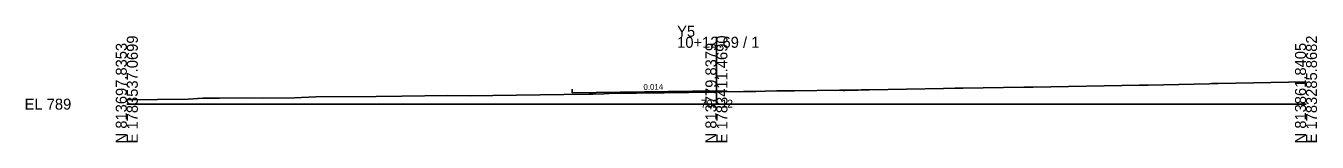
# Model space of a CAD drawing. Extents: x -26 to 1603, y -10 to 6526.
# Drawn here: x -25.7 to 302.8, y 490.3 to 520 of the extents above; entities that cross this region are included whole.
import ezdxf

# ---------------------------------------------------------------- set-up
doc = ezdxf.new("R2010")
doc.units = 0
for name, color, linetype in [('Exist Cross Section Cell', 7, 'Continuous'), ('Exist XS Center Line Elevation Label', 7, 'Continuous'), ('Exist XS Ground Line', 7, 'Continuous'), ('Prop XS Dump Level', 7, 'Continuous'), ('Prop XS EOT Tick Mark', 7, 'Continuous'), ('Prop XS Finish Grade Pavement', 7, 'Continuous'), ('Prop XS SE Text', 7, 'Continuous'), ('Prop XS Subgrade Earthwork', 7, 'Continuous')]:
    doc.layers.add(name, color=color, linetype=linetype)

msp = doc.modelspace()

# ---------------------------------------------------------------- linework, layer by layer
at = {"layer": 'Exist Cross Section Cell'}
for p, q in [((150, 500), (150, 517.15)), ((0, 500), (150, 500)), ((150, 500), (300, 500))]:
    msp.add_line(p, q, dxfattribs=at)
at = {"layer": 'Exist XS Ground Line'}
for p, q in [((118.6, 502.56), (121.36, 502.66)), ((121.36, 502.66), (122.6, 502.7)), ((122.6, 502.7), (136.75, 502.9)), ((136.75, 502.9), (142.87, 503)), ((142.87, 503), (145.78, 503.04)), ((145.78, 503.04), (147.13, 503.06)), ((147.13, 503.06), (147.98, 503.07)), ((147.98, 503.07), (148.64, 503.08)), ((148.64, 503.08), (149.03, 503.09)), ((149.03, 503.09), (150.13, 503.13)), ((150.13, 503.13), (151.42, 503.14)), ((151.42, 503.14), (156.9, 503.22)), ((156.9, 503.22), (157.33, 503.23)), ((157.33, 503.23), (157.84, 503.23)), ((157.84, 503.23), (158.63, 503.24)), ((158.63, 503.24), (160, 503.26)), ((160, 503.26), (162.37, 503.31)), ((162.37, 503.31), (165.34, 503.35)), ((165.34, 503.35), (169.83, 503.41)), ((169.83, 503.41), (181.35, 503.54)), ((181.35, 503.54), (182.42, 503.56)), ((182.42, 503.56), (186.06, 503.57)), ((186.06, 503.57), (186.81, 503.64)), ((186.81, 503.64), (188.96, 503.65)), ((188.96, 503.65), (207.8, 503.97)), ((207.8, 503.97), (210.69, 504.04)), ((210.69, 504.04), (212.68, 504.05)), ((212.68, 504.05), (228.17, 504.31)), ((228.17, 504.31), (228.65, 504.31)), ((228.65, 504.31), (230.58, 504.34)), ((230.58, 504.34), (257.63, 504.81)), ((257.63, 504.81), (258.75, 504.83)), ((258.75, 504.83), (259.82, 504.87)), ((259.82, 504.87), (275.42, 505.21)), ((275.42, 505.21), (275.99, 505.23)), ((275.99, 505.23), (276.76, 505.24)), ((276.76, 505.24), (277.68, 505.23)), ((277.68, 505.23), (300, 505.72)), ((0, 501.13), (15.64, 501.24)), ((15.64, 501.24), (19.38, 501.49)), ((19.38, 501.49), (23.54, 501.52)), ((23.54, 501.52), (30.4, 501.58)), ((30.4, 501.58), (34.56, 501.52)), ((34.56, 501.52), (42.69, 501.63)), ((42.69, 501.63), (48.07, 501.83)), ((48.07, 501.83), (63.47, 501.96)), ((63.47, 501.96), (69.97, 502.07)), ((69.97, 502.07), (81.6, 502.21)), ((81.6, 502.21), (87.33, 502.14)), ((87.33, 502.14), (93.1, 502.21)), ((93.1, 502.21), (111.14, 502.43)), ((111.14, 502.43), (117.62, 502.55)), ((117.62, 502.55), (118.6, 502.56))]:
    msp.add_line(p, q, dxfattribs=at)
at = {"layer": 'Prop XS Dump Level'}
msp.add_line((150, 503.36), (113.3, 502.84), dxfattribs=at)
at = {"layer": 'Prop XS EOT Tick Mark'}
msp.add_line((113.3, 502.84), (113.3, 503.84), dxfattribs=at)
at = {"layer": 'Prop XS Finish Grade Pavement'}
msp.add_line((113.3, 502.84), (150, 503.36), dxfattribs=at)
at = {"layer": 'Prop XS Subgrade Earthwork'}
msp.add_line((182.42, 503.28), (182.42, 503.56), dxfattribs=at)

# ---------------------------------------------------------------- texts
at = {"layer": 'Exist Cross Section Cell'}
for s, p in [('Y5', (140, 517.15)), ('10+12.69 / 1', (140, 514.35)), ('EL 789', (-26, 498.6))]:
    msp.add_text(s, height=2.8, dxfattribs=at).set_placement(p)
for s, p in [('E 1783537.0699', (2.8, 490)), ('E 1783411.4690', (152.8, 490)), ('E 1783285.8682', (302.8, 490)), ('N 813697.8353', (0, 490)), ('N 813779.8379', (150, 490)), ('N 813861.8405', (300, 490))]:
    msp.add_text(s, height=2.8, rotation=90, dxfattribs=at).set_placement(p)
at = {"layer": 'Exist XS Center Line Elevation Label'}
msp.add_text('792.12', height=2, dxfattribs=at).set_placement((146.03, 499.12))
at = {"layer": 'Prop XS SE Text'}
msp.add_text('0.014', height=1.5, rotation=0.8135, dxfattribs=at).set_placement((131.45, 503.6))

doc.saveas('drawing.dxf')
